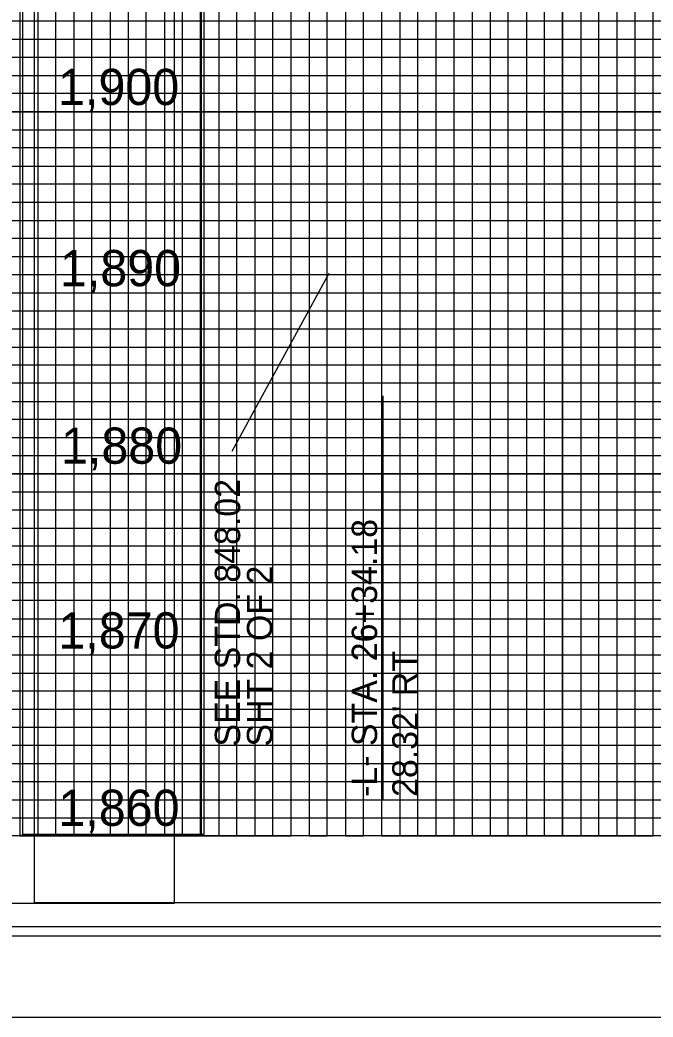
# Model space of a CAD drawing. Extents: x 557032 to 558930, y 525869 to 527437.
# Drawn here: x 558249.5 to 558424.4, y 525869.2 to 526144.6 of the extents above; entities that cross this region are included whole.
import ezdxf

# ---------------------------------------------------------------- set-up
doc = ezdxf.new("R2010")
doc.units = 0
for name, color, linetype in [('Exist Vertical Profile Vertical Axis Label', 7, 'Continuous'), ('Old_Level_63', 7, 'Continuous'), ('Prop VPI Label', 7, 'Continuous'), ('Raster_Level_4', 7, 'Continuous'), ('Sheet Cutting Line CELL', 7, 'Continuous'), ('Sheet DOT Grid CELL', 7, 'Continuous'), ('Sheet Layout Profile Border Port 2', 7, 'Continuous'), ('Sheet Plot Border Inside CELL', 7, 'Continuous'), ('Sheet Plot Border Outside CELL', 7, 'Continuous'), ('Sheet Profile CELL', 7, 'Continuous'), ('Sheet Profile Grid Major CELL', 7, 'Continuous'), ('Sheet Profile Grid Middle CELL', 7, 'Continuous'), ('Sheet Profile Grid Minor CELL', 7, 'Continuous')]:
    doc.layers.add(name, color=color, linetype=linetype)

msp = doc.modelspace()

# ---------------------------------------------------------------- linework, layer by layer
at = {"layer": 'Old_Level_63'}
for points in [[(558249.63, 526269.34), (558299.63, 526269.34), (558299.63, 525919.34), (558249.63, 525919.34)], [(558250.34, 526269.61), (558300.34, 526269.61), (558300.34, 525919.61), (558250.34, 525919.61)]]:
    msp.add_lwpolyline(points, close=True, dxfattribs=at)
at = {"layer": 'Prop VPI Label'}
for p, q in [((558334.84, 526074.57), (558308.09, 526025.35)), ((558349.84, 525929.42), (558349.84, 526040.73))]:
    msp.add_line(p, q, dxfattribs=at)
at = {"layer": 'Raster_Level_4'}
for points in [[(557947.68, 526267.12), (558292.15, 526267.12), (558292.15, 525900.58), (557947.68, 525900.58)], [(558253.56, 526235.09), (558608.2, 526235.09), (558608.2, 525900.76), (558253.56, 525900.76)]]:
    msp.add_lwpolyline(points, close=True, dxfattribs=at)
at = {"layer": 'Sheet Cutting Line CELL'}
msp.add_line((557032.45, 525869.22), (558716.45, 525869.22), dxfattribs=at)
at = {"layer": 'Sheet DOT Grid CELL'}
for p, q in [((558299.45, 526419.22), (558299.45, 525919.22)), ((558349.45, 526419.22), (558349.45, 525919.22)), ((558399.45, 526419.22), (558399.45, 525919.22)), ((557199.45, 526119.22), (558699.34, 526119.22)), ((557199.45, 526069.22), (558699.34, 526069.22)), ((557199.45, 526019.22), (558699.34, 526019.22)), ((557199.45, 525969.22), (558699.34, 525969.22))]:
    msp.add_line(p, q, dxfattribs=at)
at = {"layer": 'Sheet Layout Profile Border Port 2'}
msp.add_lwpolyline([(557249.45, 526419.22), (558649.45, 526419.22), (558649.45, 525919.22), (557249.45, 525919.22)], close=True, dxfattribs=at)
at = {"layer": 'Sheet Plot Border Inside CELL'}
msp.add_lwpolyline([(557045.45, 525891.67), (558711.95, 525891.67), (558711.95, 526946.77), (557045.45, 526946.77)], close=True, dxfattribs=at)
at = {"layer": 'Sheet Plot Border Outside CELL'}
msp.add_lwpolyline([(557032.45, 525869.22), (558716.45, 525869.22), (558716.45, 526969.22), (557032.45, 526969.22)], close=True, dxfattribs=at)
at = {"layer": 'Sheet Profile CELL'}
for p, q in [((558699.45, 525919.22), (557199.45, 525919.22)), ((557199.45, 525894.22), (558699.45, 525894.22))]:
    msp.add_line(p, q, dxfattribs=at)
msp.add_lwpolyline([(558699.45, 526944.22), (557199.45, 526944.22), (557199.45, 525894.22), (558699.45, 525894.22)], close=True, dxfattribs=at)
at = {"layer": 'Sheet Profile Grid Major CELL'}
for p, q in [((558250.52, 526119.22), (558300.52, 526119.22)), ((558249.63, 526069.22), (558299.63, 526069.22)), ((558250.52, 525969.22), (558300.52, 525969.22))]:
    msp.add_line(p, q, dxfattribs=at)
for points in [[(558249.45, 525919.22), (558299.45, 525919.22), (558299.45, 526419.22), (558349.45, 526419.22), (558349.45, 525919.22), (558399.45, 525919.22), (558399.45, 526419.22), (558449.45, 526419.22), (558449.45, 525919.22), (558499.45, 525919.22), (558499.45, 526419.22), (558549.45, 526419.22), (558549.45, 526041.24)], [(558699.45, 526119.22), (557199.45, 526119.22), (557199.45, 526069.22), (558699.45, 526069.22)], [(558542.78, 526019.22), (557199.45, 526019.22), (557199.45, 526019.22), (557199.45, 525969.22), (558699.45, 525969.22)], [(558699.45, 525919.22), (557199.45, 525919.22)]]:
    msp.add_lwpolyline(points, dxfattribs=at)
at = {"layer": 'Sheet Profile Grid Middle CELL'}
for points in [[(558224.45, 526419.22), (558274.45, 526419.22), (558274.45, 525919.22), (558324.45, 525919.22), (558324.45, 526419.22), (558374.45, 526419.22), (558374.45, 525919.22), (558424.45, 525919.22), (558424.45, 526419.22), (558474.45, 526419.22), (558474.45, 525919.22), (558524.45, 525919.22), (558524.45, 526419.22), (558574.45, 526419.22), (558574.45, 526041.24)], [(558699.45, 526144.22), (557199.45, 526144.22), (557199.45, 526094.22), (558699.45, 526094.22)], [(558699.45, 526044.22), (557199.45, 526044.22), (557199.45, 525994.22), (558699.45, 525994.22)], [(558699.45, 525944.22), (557199.45, 525944.22)]]:
    msp.add_lwpolyline(points, dxfattribs=at)
at = {"layer": 'Sheet Profile Grid Minor CELL'}
for p, q in [((557249.45, 526139.22), (558649.45, 526139.22)), ((558649.45, 526134.22), (557249.45, 526134.22)), ((557249.45, 526129.22), (558649.45, 526129.22)), ((558649.45, 526124.22), (557249.45, 526124.22)), ((557249.45, 526114.22), (558649.45, 526114.22)), ((558649.45, 526109.22), (557249.45, 526109.22)), ((557249.45, 526104.22), (558649.45, 526104.22)), ((558649.45, 526099.22), (557249.45, 526099.22)), ((557249.45, 526089.22), (558649.45, 526089.22)), ((558649.45, 526084.22), (557249.45, 526084.22)), ((557249.45, 526079.22), (558649.45, 526079.22)), ((558649.45, 526074.22), (557249.45, 526074.22)), ((557249.45, 526064.22), (558649.45, 526064.22)), ((558649.45, 526059.22), (557249.45, 526059.22)), ((557249.45, 526054.22), (558649.45, 526054.22)), ((558649.45, 526049.22), (557249.45, 526049.22)), ((557249.45, 526039.22), (558542.78, 526039.22)), ((558542.78, 526034.22), (557249.45, 526034.22)), ((557249.45, 526029.22), (558542.78, 526029.22)), ((558542.78, 526024.22), (557249.45, 526024.22)), ((557249.45, 526014.22), (558649.45, 526014.22)), ((558649.45, 526009.22), (557249.45, 526009.22)), ((557249.45, 526004.22), (558649.45, 526004.22)), ((558649.45, 525999.22), (557249.45, 525999.22)), ((557249.45, 525989.22), (558649.45, 525989.22)), ((558649.45, 525984.22), (557249.45, 525984.22)), ((557249.45, 525979.22), (558649.45, 525979.22)), ((558649.45, 525974.22), (557249.45, 525974.22)), ((557249.45, 525964.22), (558649.45, 525964.22)), ((558649.45, 525959.22), (557249.45, 525959.22)), ((557249.45, 525954.22), (558649.45, 525954.22)), ((558649.45, 525949.22), (557249.45, 525949.22)), ((557249.45, 525939.22), (558649.45, 525939.22)), ((558649.45, 525934.22), (557249.45, 525934.22)), ((557249.45, 525929.22), (558649.45, 525929.22)), ((557249.45, 525924.22), (558649.45, 525924.22))]:
    msp.add_line(p, q, dxfattribs=at)
for points in [[(558254.45, 526419.22), (558254.45, 525919.22), (558259.45, 525919.22), (558259.45, 526419.22)], [(558264.45, 526419.22), (558264.45, 525919.22), (558269.45, 525919.22), (558269.45, 526419.22)], [(558279.45, 526419.22), (558279.45, 525919.22), (558284.45, 525919.22), (558284.45, 526419.22)], [(558289.45, 526419.22), (558289.45, 525919.22), (558294.45, 525919.22), (558294.45, 526419.22)], [(558304.45, 526419.22), (558304.45, 525919.22), (558309.45, 525919.22), (558309.45, 526419.22)], [(558314.45, 526419.22), (558314.45, 525919.22), (558319.45, 525919.22), (558319.45, 526419.22)], [(558329.45, 526419.22), (558329.45, 525919.22), (558334.45, 525919.22), (558334.45, 526419.22)], [(558339.45, 526419.22), (558339.45, 525919.22), (558344.45, 525919.22), (558344.45, 526419.22)], [(558354.45, 526419.22), (558354.45, 525919.22), (558359.45, 525919.22), (558359.45, 526419.22)], [(558364.45, 526419.22), (558364.45, 525919.22), (558369.45, 525919.22), (558369.45, 526419.22)], [(558379.45, 526419.22), (558379.45, 525919.22), (558384.45, 525919.22), (558384.45, 526419.22)], [(558389.45, 526419.22), (558389.45, 525919.22)], [(558389.45, 525919.22), (558394.45, 525919.22), (558394.45, 526419.22)], [(558404.45, 526419.22), (558404.45, 525919.22), (558409.45, 525919.22), (558409.45, 526419.22)], [(558414.45, 526419.22), (558414.45, 525919.22), (558419.45, 525919.22), (558419.45, 526419.22)]]:
    msp.add_lwpolyline(points, dxfattribs=at)

# ---------------------------------------------------------------- texts
at = {"layer": 'Exist Vertical Profile Vertical Axis Label'}
for s, p in [('1,900', (558260.08, 526121.07)), ('1,890', (558260.59, 526071.04)), ('1,880', (558260.89, 526022.01)), ('1,870', (558260.17, 525970.99)), ('1,860', (558260.17, 525922.01))]:
    msp.add_text(s, height=10, dxfattribs=at).set_placement(p)
at = {"layer": 'Prop VPI Label'}
for s, p in [('SEE STD. 848.02 ', (558310.38, 525943.92)), ('-L- STA. 26+34.18', (558348.2, 525930.01)), ('SHT 2 OF 2', (558319.25, 525943.92)), ("28.32' RT", (558359.4, 525930.01))]:
    msp.add_text(s, height=7, rotation=90, dxfattribs=at).set_placement(p)

doc.saveas('drawing.dxf')
